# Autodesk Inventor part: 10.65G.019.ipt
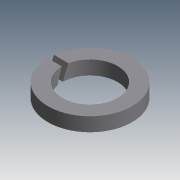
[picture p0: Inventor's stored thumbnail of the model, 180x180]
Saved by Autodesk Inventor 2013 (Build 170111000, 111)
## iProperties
Shininess: 25.0
Length Units: 11269
Angle Units: 11279
Time Units: 11290
Mass Units: 11283
Length Display Precision: 3
Angle Display Precision: 2
Created: 2001-04
Part Number: 10.65G.019.ipt
Material: Steel, Mild
Document SubType Name: Modeling
Designer: tevgeniy
Mass: 1.96655 g
Surface Area: 4.06504 cm^2
Volume: 0.250197 cm^3
Density: 7.86 g/cm^3
Density: 7.86
Volumn: 0.2501956736428592
Area: 4.065041569612211
PropertySet Name: Model Information
Control State: 0
Master: False
Checked Out: False
Last Check In Date: 2008-10-15
Checked Out Date: 2008-10-15
Author: tevgeniy
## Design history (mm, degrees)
node "ExtrusionBlind1" dims "d2" = 2.5, "d3" = 0
  sketch "Sketch1"
    geometry: C1 r 7.6 at (-266.435, -313.047)
    constraints: 1 centre point, 1 other
    dimensions: "d1" = 15.2 diameter of C1
node "Hole1" dims "d5" = 10, "d6" = 4, "d7" = 2, "d8" = 60 deg, "d9" = 8, "d10" = 118 deg
  sketch "Sketch2"
    geometry: C1 r 7.6 at (0, 0) reference
node "WorkPlane1"
node "ExtrusionToFace1" dims "d18" = 0.13, "d19" = 0
  sketch "Sketch3"
    geometry: L1 (-21.641, 0.09)-(-21.641, -1); L2 (-19.141, 1)-(-21.641, 0.09); L3 (-19.141, -0.09)-(-19.141, 1); L4 (-21.641, -1)-(-19.141, -0.09); L5 (-9.571, 0)-(-31.211, 0); C1 r 7.6 at (-19.141, 0); C2 r 7.6 at (-21.641, 0)
    constraints: 10 end point, 2 centre point, 2 parallel, 1 vertical
    dimensions: "d13" = 0 horizontal distance of L2.start C1.centre; "d15" = 0 horizontal distance of L1.start C2.centre; "d17" = 160 deg angle of L4 L5
body "Solid1"
other parameters: "d0" = 15.2 (derived), "d4" = 0, "d12" = 0 (derived), "d14" = 0 (derived), "d16" = 160 deg (derived), "d20" = 0
